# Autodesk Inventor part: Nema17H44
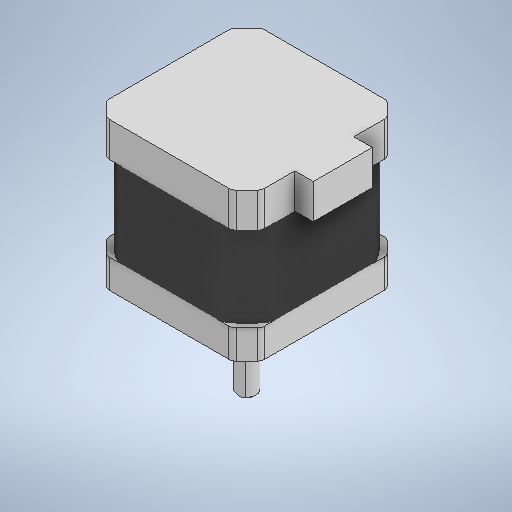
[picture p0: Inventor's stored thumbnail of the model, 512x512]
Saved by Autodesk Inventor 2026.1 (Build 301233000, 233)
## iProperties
Created: 2025-12
Part Number: Nema17H44
Material: Типовые
Document SubType Name: Modeling
Designer: Yury Melnikov
Density: 1 g/cm^3
Appearance: По умолчанию
Author: Yury Melnikov
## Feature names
1. Выдавливание1 [Extrusion]
2. Выдавливание2 [Extrusion]
3. Выдавливание3 [Extrusion]
4. Сопряжение2 [Fillet]
5. Сдвиг1
6. Круговой массив1 [Circular Pattern]
7. Выдавливание4 [Extrusion]
8. Сопряжение3 [Fillet]
9. Выдавливание5 [Extrusion]
10. Фаска2 [Chamfer]
11. Выдавливание6 [Extrusion]
12. Выдавливание7 [Extrusion]
## Parameters: d0 = 42 mm, d1 = 42 mm, d2 = 4 mm, d3 = 4 mm, d4 = 4 mm, d5 = 4 mm, d6 = 4 mm, d7 = 4 mm, d8 = 4 mm, d9 = 4 mm, d10 = 2 mm, d11 = 9.4 mm, d12 = 0, d14 = 42 mm, d15 = 7 mm, d16 = 7 mm, d17 = 7 mm, d18 = 7 mm, d19 = 7 mm, d20 = 7 mm, d21 = 7 mm, d22 = 7 mm, d26 = 360 deg, d28 = 22.9 mm, d29 = 0, d30 = 7.8 mm, d31 = 0, d32 = 3 mm, d35 = 0.229 mm, d38 = 0.458 mm, d43 = -11.5 mm, d44 = -15.75 mm, d45 = 0, d46 = 0, d48 = 360 deg, d50 = 22 mm, d51 = 1.9 mm, d52 = 0, d53 = 1 mm, d54 = 9 mm, d55 = 5 mm, d57 = 26.3 mm, d58 = 0, d62 = 0.6 mm, d63 = 2 mm, d64 = 45 deg, d65 = 4.4 mm, d66 = 22.1 mm, d67 = 0, d68 = 5 mm, d69 = 16 mm, d70 = 22.1 mm, d71 = 0
